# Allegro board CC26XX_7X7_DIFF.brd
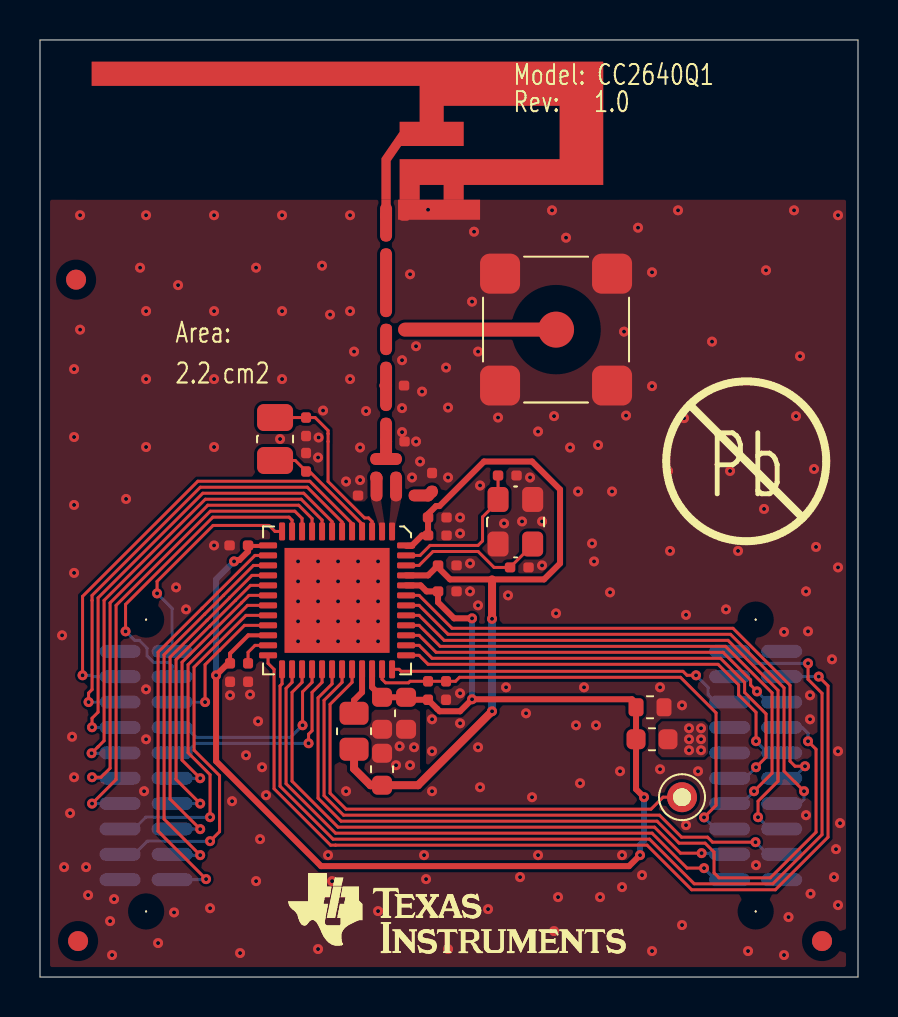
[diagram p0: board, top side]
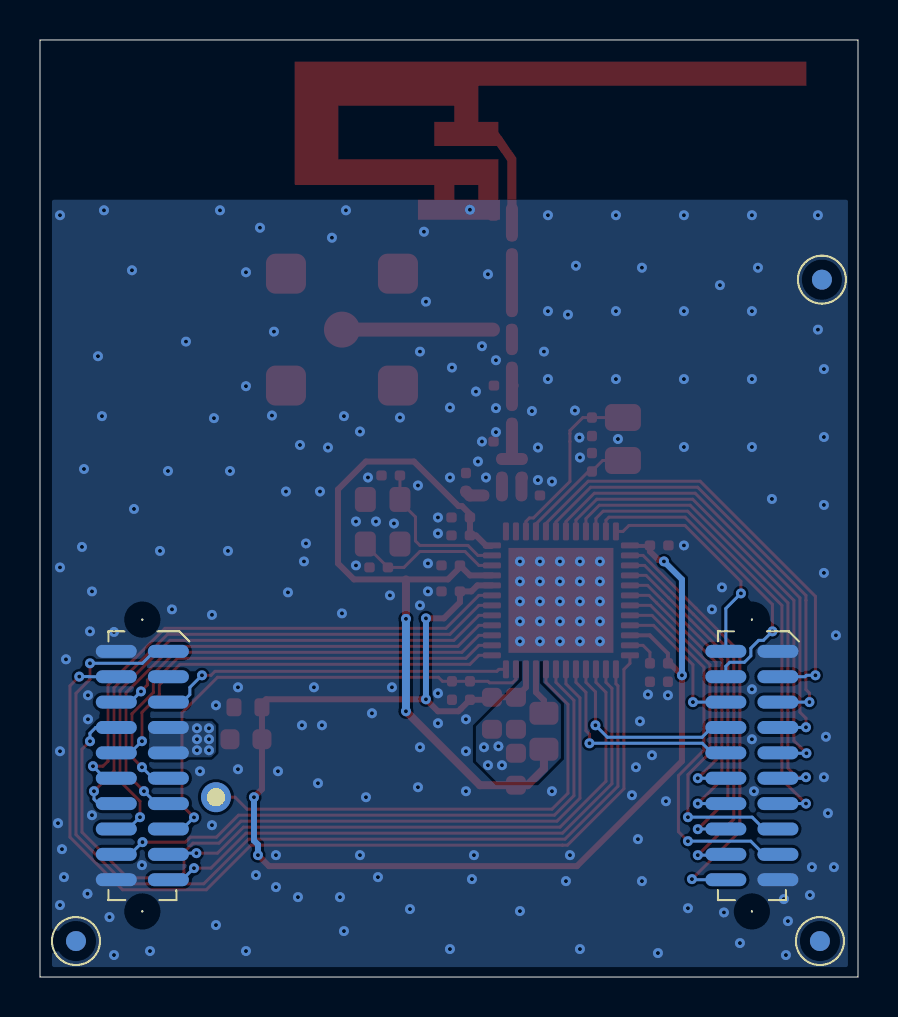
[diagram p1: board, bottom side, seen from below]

Outline 40.9 x 46.9 mm; copper layers: TOP, BOTTOM. Coordinates in mm from the lower left corner of the outline.
Outline path: 0,46.9 0,0 40.9,0 40.9,46.9 0,46.9

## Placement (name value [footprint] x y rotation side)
A1  2.4GHz  [ANTENNA_DN007AN]  17.3 38.65 0 top
C2  DNM  [CAPC1608X90L]  29.8 13.5 0 top
C3  100nF  [CAPC1005X60B2N]  10.4 21.6 180 top
C4  100nF  [CAPC1005X60B2N]  9.5 15.7 270 top
C5  100nF  [CAPC1005X60B2N]  19.9 19.3 0 top
C6  10uF  [CAPC1608X100A2N]  17.1 14 270 top
C7  100nF  [CAPC1608X90A2N]  18.3 14 270 top
C8  10uF  [CAPC1608X100A2N]  17.1 9.6 90 top
C9  100nF  [CAPC1005X60B2N]  19.9 20.6 0 top
C10  DNM_0402  [CAPC1005X60B2N]  19.4 23 0 top
C11  1pF  [CAPC1005X60B2N]  17.8 25 90 top
C12  DNM_0402  [CAPC1005X60B2N]  17.3 26.8 0 top
C13  1pF  [CAPC1005X60B2N]  18.2 29.6 180 top
C14  12pF  [CAPC1005X60B2N]  17.3 32.4 90 top
C15  DNM_0402  [CAPC1005X60B2N]  17.3 38.1 0 top
C16  100nF  [CAPC1005X60B2N]  19.4 22.1 0 top
C17  16pF  [CAPC1005X60B2N]  13.3 28 270 top
C18  16pF  [CAPC1005X60B2N]  13.3 25.3 90 top
C19  1uF  [CAPC1005X60B2N]  10.4 15.7 270 top
C20  100nF  [CAPC1005X60B2N]  20.3 14.8 270 top
C21  1pF  [CAPC1005X60B2N]  15.9 24.1 0 top
C22  DNM_0402  [CAPC1005X60B2N]  23.5 20.5 0 top
C23  DNM_0402  [CAPC1005X60B2N]  22.9 25.1 0 top
C24  DNM_0402  [CAPC1005X60B2N]  18.25 32.4 180 top
C31  6.8pF  [CAPC1005X60B2N]  19.6 24.3 90 top
DIO22  TP_0.9mm_PTH  [TP150_90H]  32.1 9 0 top
FIDU1  FIDU_1MM  [FID100X115]  1.9 1.8 0 top
FIDU2  FIDU_1MM  [FID100X115]  39.1 1.8 0 top
FIDU3  FIDU_1MM  [FID100X115]  1.8 34.9 0 top
FIDU4  FIDU_1MM  [FID100X115]  1.9 1.8 180 bottom
FIDU5  FIDU_1MM  [FID100X115]  39.1 1.8 180 bottom
FIDU6  FIDU_1MM  [FID100X115]  1.8 34.9 180 bottom
FL1  BLM18HE152SZ1  [FILC1608X100A2N]  31.4 11.9 180 top
J1  SMA-10V21-TGG  [HUSTSAN_SMA10V21TGGAN]  25.8 32.4 0 top
L1  10uH  [INDC2012X150A2N]  15.7 13.2 270 top
L11  2.4nH  [INDC1005X60B2N]  17.8 24.1 0 top
L12  2nH  [INDC1005X60B2N]  17.3 27.7 90 top
L13  2nH  [INDC1005X60B2N]  17.3 30.5 90 top
L21  2.4nH  [INDC1005X60B2N]  16.8 25 90 top
NOREF  -  []  32.36 0 90 top
NOREF#2  -  []  0 44.07 0 top
P1  SFM-110-02-S-D-A-K-TR  [SAMTEC_SFM11002AN]  4 16.3 0 bottom
P2  SFM-110-02-S-D-A-K-TR  [SAMTEC_SFM11002AN]  34.48 16.3 0 bottom
R1  100k  [RESC1005X40B2N]  19.4 14.8 270 top
R12  0  [RESC1005X40B2N]  17.3 37.1 270 top
U1  CC2640R2FTWRGZRQ1  [QFNFC50P700X700X100-49A2N]  17.6 22.3 180 top
UNK#REFDES  -  []  13.4 5.2 0 top
UNK#REFDES#2  #VALUE  []  31.1 21.6 0 top
Y1  32.768kHz  [XTAL_FC13A_A2N]  11.75 28 270 top
Y2  24MHz  [OSCCC250X320X60-4L]  22.9 23.9 270 top

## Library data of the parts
A1 = ANTENNA_DN007
C2 = CAPACITOR: alternate symbols: (CAPC1608X90L,CAPC1608X90M)
C3-C5 C9-C24 C31 = CAPACITOR: User Part Number: #PN
C6 C8 = CAPACITOR: User Part Number: #PN; alternate symbols: (CAPC1608X100A2L,CAPC1608X100A2M)
C7 = CAPACITOR: User Part Number: #PN; alternate symbols: (CAPC1608X90A2L,CAPC1608X90A2M)
DIO22 = TEST_POINT
FIDU1-FIDU6 = FIDMARK
FL1 = FILTER_FERRITE: User Part Number: #PN; alternate symbols: (FILC1608X100A2L,FILC1608X100A2M)
J1 = CONN_COAX_1+4: alternate symbols: (HUSTSAN_SMA10V21TGGL,HUSTSAN_SMA10V21TGGM)
L1 = IND_CORE: User Part Number: #PN; alternate symbols: (INDC2012X150A2L,INDC2012X150A2M)
L11-L13 L21 = INDUCTOR: User Part Number: #PN
P1 P2 = CONN_HEADER_2X10_P_S
R1 R12 = RESISTOR: User Part Number: #PN; alternate symbols: (RESC1005X40B2L,RESC1005X40B2M)
U1 = IC_RF_CC26XX_QFN48_V2: User Part Number: #PN; alternate symbols: (QFNFC50P700X700X100-49A2L,QFNFC50P700X700X100-49A2M)
UNK#REFDES#2 = -: User Part Number: #PN
Y1 = CRYSTAL: User Part Number: #PN; alternate symbols: (XTAL_FC13A_A2L,XTAL_FC13A_A2M)
Y2 = XTAL_4PIN_S: alternate symbols: (OSCCC250X320X60-4L,OSCCC250X320X60-4M)

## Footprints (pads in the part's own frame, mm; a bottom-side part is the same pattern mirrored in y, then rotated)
ANTENNA_DN007AN
  rect 0.46x0.5 smd: 1(0,0)
  rect 1x0.5 smd: 2(1.18,0) 3(3.38,0)
CAPC1005X60B2N
  custom 0.125x0.125 smd: 1(0,0) 2(0.924,0)
CAPC1608X90A2N
  custom 0.237x0.237 smd: 1(0,0) 2(1.6,0)
CAPC1608X90L
  custom 0.188x0.188 smd: 1(0,0) 2(1.4,0)
CAPC1608X100A2N
  custom 0.237x0.237 smd: 1(0,0) 2(1.6,0)
FID100X115
  round 1 smd: 1(0,0)
FILC1608X100A2N
  custom 0.237x0.237 smd: 1(0,0) 2(1.6,0)
HUSTSAN_SMA10V21TGGAN
  round 1.801 smd: 1(0,0)
  custom 0.5x0.5 smd: 2(-2.8,-2.8) 3(2.8,-2.8) 4(2.8,2.8) 5(-2.8,2.8)
INDC1005X60B2N
  custom 0.125x0.125 smd: 1(0,0) 2(0.924,0)
INDC2012X150A2N
  custom 0.287x0.287 smd: 1(0,0) 2(1.8,0)
OSCCC250X320X60-4L
  custom 0.263x0.263 smd: 1(0,0) 2(2.23,0) 3(2.23,1.73) 4(0,1.73)
QFNFC50P700X700X100-49A2N
  custom 0.075x0.075 smd: 1(0,0) 2(0.5,0) 3(1,0) 4(1.5,0) 5(2,0) 6(2.5,0) 7(3,0) 8(3.5,0) 9(4,0) 10(4.5,0) 11(5,0) 12(5.5,0) 13(6.2,0.7) 14(6.2,1.2) 15(6.2,1.7) 16(6.2,2.2) 17(6.2,2.7) 18(6.2,3.2) 19(6.2,3.7) 20(6.2,4.2) 21(6.2,4.7) 22(6.2,5.2) 23(6.2,5.7) 24(6.2,6.2) 25(5.5,6.9) 26(5,6.9) 27(4.5,6.9) 28(4,6.9) 29(3.5,6.9) 30(3,6.9) 31(2.5,6.9) 32(2,6.9) 33(1.5,6.9) 34(1,6.9) 35(0.5,6.9) 36(0,6.9) 37(-0.7,6.2) 38(-0.7,5.7) 39(-0.7,5.2) 40(-0.7,4.7) 41(-0.7,4.2) 42(-0.7,3.7) 43(-0.7,3.2) 44(-0.7,2.7) 45(-0.7,2.2) 46(-0.7,1.7) 47(-0.7,1.2) 48(-0.7,0.7)
  rect 5.25x5.25 smd: 49(2.75,3.45)
RESC1005X40B2N
  custom 0.125x0.125 smd: 1(0,0) 2(0.924,0)
SAMTEC_SFM11002AN
  round 0.099 hole 1.501 unplated: (1.302,-1.588) (1.302,13.017)
  oval 2.05x0.65 smd: 1(0,0) 2(2.604,0) 3(0,1.27) 4(2.604,1.27) 5(0,2.54) 6(2.604,2.54) 7(0,3.81) 8(2.604,3.81) 9(0,5.08) 10(2.604,5.08) 11(0,6.35) 12(2.604,6.35) 13(0,7.62) 14(2.604,7.62) 15(0,8.89) 16(2.604,8.89) 17(0,10.16) 18(2.604,10.16) 19(0,11.43) 20(2.604,11.43)
TP150_90H
  round 1.5 hole 0.9: 1(0,0)
XTAL_FC13A_A2N
  custom 0.338x0.338 smd: 1(0,0) 2(2.15,0)

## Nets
GND: A1.2(GND_2) A1.3(GND_3) C2.2 C3.2 C4.2 C5.2 C6.2 C7.2 C8.2 C9.2 C10.2 C12.2 C13.1 C15.2 C16.2 C17.2 C18.2 C19.2 C20.2 C21.1 C22.2 C23.2 C31.2 J1.2 J1.3 J1.4 J1.5 P1.1 P1.19 P2.2 P2.20 U1.49(VSS) Y2.2 Y2.4
VDD_EB: FL1.1 P2.7 P2.9
VDDR: C8.1 C9.1 C10.1 C16.1 L1.2 U1.45(VDDR#45) U1.48(VDDR#48)
VDDS: C2.1 C3.1 C4.1 C5.1 C6.1 C7.1 FL1.2 R1.2 U1.13(VDDS2) U1.22(VDDS3) U1.34(VDDS_DCDC) U1.44(VDDS)
DCDC_SW: L1.1 U1.33(DCDC_SW)
DIO_0: P1.3 U1.5(DIO_0)
DIO_1: P1.5 U1.6(DIO_1)
DIO_2: P1.7 U1.7(DIO_2)
DIO_3: P1.9 U1.8(DIO_3)
DIO_4: P1.11 U1.9(DIO_4)
DIO_5: P1.13 U1.10(DIO_5)
DIO_6: P1.4 U1.11(DIO_6)
DIO_7: P1.2 U1.12(DIO_7)
DIO_8: P1.20 U1.14(DIO_8)
DIO_9: P1.18 U1.15(DIO_9)
DIO_10: P1.16 U1.16(DIO_10)
DIO_11: P1.14 U1.17(DIO_11)
DIO_12: P1.12 U1.18(DIO_12)
DIO_13: P1.15 U1.19(DIO_13)
DIO_14: P1.17 U1.20(DIO_14)
DIO_15: P1.6 U1.21(DIO_15)
DIO_16 / JTAG TDO: P2.19 U1.26(DIO_16)
DIO_17 / JTAG TDI: P2.17 U1.27(DIO_17)
DIO_18: P1.8 U1.28(DIO_18)
DIO_19: P1.10 U1.29(DIO_19)
DIO_20: P2.8 U1.30(DIO_20)
DIO_21: P2.18 U1.31(DIO_21)
DIO_22: DIO22.1 U1.32(DIO_22)
DIO_23: P2.5 U1.36(DIO_23)
DIO_24: P2.10 U1.37(DIO_24)
DIO_25: P2.11 U1.38(DIO_25)
DIO_26: P2.6 U1.39(DIO_26)
DIO_27: P2.13 U1.40(DIO_27)
DIO_28: P2.16 U1.41(DIO_28)
DIO_29: P2.14 U1.42(DIO_29)
DIO_30: P2.12 U1.43(DIO_30)
JTAG_TCK: P2.1 U1.25(JTAG_TCKC)
JTAG_TMS: P2.4 U1.24(JTAG_TMSC)
NRESET: C20.1 P2.15 R1.1 U1.35(RESET_N)
N310466: C23.1 U1.47(X24M_P) Y2.1
N310868: C22.1 U1.46(X24M_N) Y2.3
N314427: C21.2 L21.1 U1.2(RF_N)
N314470: C11.1 L11.1 U1.1(RF_P)
N314514: C31.1 L11.2
N314764: C11.2 C12.1 L12.1 L21.2
N315193: C13.2 L12.2 L13.1
N316022: A1.1(FEED_1) C15.1 R12.1
N316040: C24.1 J1.1
N316649: C19.1 U1.23(DCOUPL)
N316919: C17.1 U1.3(X32K_Q1) Y1.1
N316932: C18.1 U1.4(X32K_Q2) Y1.2
N334495: C14.1 C24.2 L13.2
N356130: C14.2 R12.2

Pads without a net: FIDU1 1; FIDU2 1; FIDU3 1; FIDU4 1; FIDU5 1; FIDU6 1; P2 3

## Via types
v1: diameter 0.5, hole 0.2, TOP to BOTTOM, 260 vias

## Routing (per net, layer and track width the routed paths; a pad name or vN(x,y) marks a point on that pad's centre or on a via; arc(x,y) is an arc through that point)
GND:
  vias: v1(1.1,17.1) v1(1.2,5.5) v1(1.5,8.2) v1(1.6,12.02) v1(1.7,30.42) v1(1.7,27.02) v1(1.7,23.62) v1(1.7,20.22) v1(1.7,10) v1(2,38.12) v1(2,32.4) v1(2.3,5.5) v1(2.4,4.1) v1(3.5,2.8) v1(3.6,1.1) v1(3.7,3.9) v1(4.3,23.92) v1(5,35.5) v1(5.2,9.3) v1(5.3,38.12) v1(5.3,33.33) v1(5.3,29.92) v1(5.3,26.52) v1(5.3,14.4) v1(5.3,11.9) v1(5.9,1.7) v1(6.7,3.23) v1(6.8,19.5) v1(6.9,34.62) v1(7.3,18.4) v1(8.5,3.44) v1(8.7,38.12) v1(8.7,33.33) v1(8.7,29.92) v1(8.7,26.52) v1(8.7,21.6) v1(9.5,14.1) v1(9.6,8.8) v1(10,1.2) v1(10.3,11.1) v1(10.5,14.14) v1(10.8,35.5) v1(10.8,4.8) v1(10.9,12.8) v1(11,6.9) v1(11.1,10.5) v1(11.3,9.1) v1(12,26.92) v1(12.1,38.12) v1(12.1,33.33) v1(12.1,29.92) v1(12.9,20.8) v1(12.9,19.8) v1(12.9,18.8) v1(12.9,17.8) v1(12.9,16.8) v1(13.93,27) v1(13.9,26) v1(13.9,20.8) v1(13.9,19.8) v1(13.9,18.8) v1(13.9,17.8) v1(13.9,16.8) v1(13.9,1.4) v1(14.1,35.6) v1(14.15,28.35) v1(14.4,6.1) v1(14.5,33.15) v1(14.6,4.8) v1(14.9,20.8) v1(14.9,19.8) v1(14.9,18.8) v1(14.9,17.8) v1(14.9,16.8) v1(15.3,24.8) v1(15.3,9.3) v1(15.5,38.12) v1(15.5,33.33) v1(15.5,29.92) v1(15.7,31.3) v1(15.9,20.8) v1(15.9,19.8) v1(15.9,18.8) v1(15.9,17.8) v1(15.9,16.8) v1(16,26.5) v1(16,24.87) v1(16.3,28.33) v1(16.9,20.8) v1(16.9,19.8) v1(16.9,18.8) v1(16.9,17.8) v1(16.9,16.8) v1(16.9,3.3) v1(17.8,10.6) v1(17.98,11.55) v1(18.1,30.87) v1(18.1,28.47) v1(18.1,27.27) v1(18.5,35.17) v1(18.5,10.6) v1(18.6,25) v1(18.7,11.5) v1(18.8,31.57) v1(18.8,26.8) v1(19,25.8) v1(19.1,29.3) v1(19.2,6.1) v1(19.3,4.9) v1(19.4,38.4) v1(19.6,12.9) v1(19.6,11.3) v1(19.6,9.3) v1(20.3,30.5) v1(20.4,28.5) v1(20.4,25) v1(20.4,1.4) v1(21,23) v1(21,22.2) v1(21,14.2) v1(21,12.7) v1(21.5,20.7) v1(21.5,19.3) v1(21.6,33.8) v1(21.7,37.3) v1(21.9,31.3) v1(21.9,18.6) v1(21.9,11.5) v1(22,24.6) v1(22,9.5) v1(22.4,3.4) v1(22.9,28) v1(23.2,22.7) v1(23.3,14.5) v1(23.4,19.1) v1(24,5) v1(24.1,22.8) v1(24.3,13.2) v1(24.5,25) v1(24.6,9) v1(24.9,27.3) v1(24.9,6.1) v1(25.1,22.8) v1(25.1,20.6) v1(25.6,38.37) v1(25.7,28.07) v1(25.7,2.3) v1(25.8,18.2) v1(25.9,4) v1(26.3,37) v1(26.5,26.5) v1(26.8,12.6) v1(26.9,24.3) v1(27,9.7) v1(27.2,14.5) v1(27.6,21.7) v1(27.7,20.8) v1(27.8,12.6) v1(27.9,26.62) v1(28,4) v1(28.5,19.25) v1(28.6,24.3) v1(29,10.3) v1(29.1,6.1) v1(29.1,4.5) v1(29.2,32.3) v1(29.3,28.1) v1(29.9,37.5) v1(30.1,5.1) v1(30.6,35.27) v1(30.6,29.57) v1(30.6,1.3) v1(31,14.5) v1(31,10.4) v1(31.4,25.33) v1(31.5,21.33) v1(31.9,38.37) v1(32.1,13.6) v1(32.1,2.6) v1(32.2,27.97) v1(32.3,18.12) v1(32.3,7.6) v1(32.9,10.3) v1(33.6,31.8) v1(34.3,18.4) v1(34.5,25.33) v1(34.9,21.33) v1(35.4,1.3) v1(35.8,5.6) v1(36.2,23.42) v1(36.3,35.37) v1(37.2,17.27) v1(37.2,1.1) v1(37.43,3) v1(37.7,38.37) v1(37.8,28.07) v1(38,31.07) v1(38.3,19.3) v1(38.3,8.1) v1(38.4,17.3) v1(38.5,14.1) v1(38.5,12.9) v1(38.53,4.17) v1(38.7,25.42) v1(38.8,21.52) v1(39.6,15.9) v1(39.7,5) v1(39.8,6.4) v1(39.9,38.12) v1(39.9,20.5) v1(39.9,11.3) v1(39.9,3.6) v1(40,7.7)
VDD_EB:
  vias: v1(32.45,12.45) v1(32.45,11.9) v1(32.45,11.35) v1(33.05,12.45) v1(33.05,11.9) v1(33.05,11.35)
VDDR: length 39.3
  TOP w0.15: U1.48 18.33,21.58
  TOP w0.3: U1.45 19.4,20.1 C9.1 19.9,20.5 20.5,19.9 25.2,19.9 26,20.7 26,24.4 24.6,25.8 22.2,25.8 19.97,23.57 19.8,23.57 19.4,23.17 C10.1 C16.1 19.1,22.1 18.58,21.58 18.33,21.58
  TOP w0.4: v1(22.6,17.93) 22.6,19.9 ; v1(22.6,13.3) 18.9,9.6 C8.1 16.53,9.6 15.7,10.42 L1.2
  BOTTOM w0.4: v1(22.6,13.3) v1(22.6,17.93)
VDDS: length 71
  TOP w0.15: U1.34 16.6,15.35 ; U1.13 11.38,21.58
  TOP w0.2: U1.22 10.41,17.1 9.5,16.19 C4.1 ; 11.38,21.58 10.43,21.58 C3.1
  TOP w0.3: C4.1 9.41,15.7 v1(8.8,15.1) 8.8,10.8 14.05,5.55 29.45,5.55 v1(30,6.1) ; C3.1 10.4,21.3 9.98,20.87 9.78,20.87 v1(9.7,20.8) ; U1.44 19.03,19.6 19.33,19.3 C5.1 19.9,18.75 20.71,17.95 v1(21.6,17.95) ; 16.6,15.35 16.6,14.5 C6.1 C7.1 18.43,13.88 R1.2 19.86,13.42 19.98,13.3 21,13.3 v1(21.6,13.9) 29.6,13.9 29.8,13.69 C2.1 FL1.2 29.8,9.4 v1(30.2,9)
  BOTTOM w0.3: v1(9.7,20.8) 8.8,19.9 v1(8.8,15.1) ; v1(21.6,13.9) v1(21.6,17.95) ; v1(30,6.1) 30,6.63 30.2,6.83 v1(30.2,9)
DCDC_SW: length 2.4
  TOP w0.15: U1.33 16.1,15.35
  TOP w0.3: 16.1,15.35 16.1,14.25 15.7,13.85 L1.1
DIO_0: length 23
  TOP w0.15: v1(2.13,15.1) 2.13,19.05 7.89,24.81 13.49,24.81 15.6,22.7 U1.5
  BOTTOM w0.15: v1(2.13,15.1) 2.58,15.1 2.65,15.03 P1.3
DIO_1: length 22.9
  TOP w0.15: U1.6 15.1,22.77 13.37,24.51 8.02,24.51 2.6,19.1 2.6,18.85 2.6,18.85 2.6,14.39 2.43,14.21 v1(2.43,13.76)
  BOTTOM w0.15: v1(2.43,13.76) P1.5
DIO_2: length 23
  TOP w0.15: U1.7 14.6,22.79 13.19,24.21 8.14,24.21 2.9,18.97 2.9,13.25 2.6,12.95 v1(2.6,12.5)
  BOTTOM w0.15: P1.7 2.81,12.49 2.8,12.5 v1(2.6,12.5)
DIO_3: length 23.3
  TOP w0.15: v1(2.58,11.2) 2.9,11.52 3.2,11.82 3.2,18.85 8.27,23.91 13.06,23.91 14.1,22.87 U1.8
  BOTTOM w0.15: v1(2.58,11.2) 3.98,11.2 P1.9
DIO_4: length 23.8
  TOP w0.15: U1.9 13.6,22.94 12.94,23.61 8.39,23.61 3.5,18.72 3.5,10.45 3.05,10 v1(2.6,10)
  BOTTOM w0.15: P1.11 2.85,9.95 2.8,10 v1(2.6,10)
DIO_5: length 23.9
  TOP w0.15: U1.10 13.1,22.95 12.74,23.31 8.52,23.31 3.8,18.6 3.8,9.88 v1(2.6,8.68)
  BOTTOM w0.15: P1.13 v1(2.6,8.68)
DIO_6: length 15.9
  TOP w0.15: v1(4.28,17.3) 4.28,18.65 8.64,23.01 12.45,23.01 12.6,22.86 U1.11
  BOTTOM w0.15: v1(4.28,17.3) 4.73,16.85 4.96,16.85 5.36,16.46 5.36,16.07 5.68,15.75 6.42,15.75 6.61,15.56 P1.4
DIO_7: length 11.3
  TOP w0.15: v1(5.85,19.2) 5.85,19.8 8.65,22.6 11.45,22.6 11.75,22.3 U1.12
  BOTTOM w0.15: P1.2 6.61,18.45 v1(5.85,19.2)
DIO_8: length 21.6
  TOP w0.15: U1.14 10.75,21.1 8.88,19.23 5.9,16.26 5.9,7.3 v1(8.3,4.9)
  BOTTOM w0.15: v1(8.3,4.9) 8.27,4.87 P1.20
DIO_9: length 19.2
  TOP w0.15: U1.15 10.67,20.6 9.18,19.1 9.18,19.1 8.23,18.16 6.2,16.13 6.2,7.91 v1(8.01,6.1)
  BOTTOM w0.15: v1(8.01,6.1) 6.65,6.1 P1.18
DIO_10: length 17.2
  TOP w0.15: v1(8.01,7.4) 6.5,8.91 6.5,16.01 8.36,17.86 8.36,17.86 9.48,18.98 9.48,18.98 10.6,20.1 U1.16
  BOTTOM w0.15: v1(8.01,7.4) 7.84,7.4 7.84,7.41 P1.16
DIO_11: length 15.2
  TOP w0.15: v1(8.01,8.68) 6.8,9.89 6.8,15.88 8.48,17.56 8.48,17.56 9.78,18.85 10.52,19.6 U1.17
  BOTTOM w0.15: v1(8.01,8.68) P1.14
DIO_12: length 13.3
  TOP w0.15: v1(8.01,9.95) 7.1,10.86 7.1,15.76 8.61,17.26 10.45,19.1 U1.18
  BOTTOM w0.15: v1(8.01,9.95) P1.12
DIO_13: length 18.1
  TOP w0.15: U1.19 10.37,18.6 8.73,16.96 7.4,15.63 7.4,11.23 8.5,10.13 v1(8.5,8)
  BOTTOM w0.15: v1(8.5,8) 5.29,8 4.7,7.41 P1.15
DIO_14: length 19
  TOP w0.15: U1.20 10.3,18.1 8.86,16.66 8.86,16.66 7.7,15.51 7.7,11.35 8.98,10.08 8.98,7.27 v1(8.5,6.8)
  BOTTOM w0.15: v1(8.5,6.8) 5.36,6.8 4.7,6.14 P1.17
DIO_15: length 7.5
  TOP w0.15: U1.21 10.22,17.6 8.98,16.36 8.98,16.36 8.25,15.63 v1(8.25,13.76)
  BOTTOM w0.15: P1.6 v1(8.25,13.76)
DIO_16 / JTAG TDO: length 30
  TOP w0.15: v1(33.2,5.45) 32.35,5.45 30.6,7.2 14.78,7.2 12.3,9.67 12.3,14.45 12.6,14.75 U1.26
  BOTTOM w0.15: P2.19 33.78,4.87 v1(33.2,5.45)
DIO_17 / JTAG TDI: length 29.2
  TOP w0.15: v1(33.08,6.2) 32.03,6.2 30.73,7.5 14.9,7.5 12.6,9.8 12.6,14.25 13.1,14.75 U1.27
  BOTTOM w0.15: P2.17 33.78,6.14 33.72,6.2 v1(33.08,6.2)
DIO_18: length 10
  TOP w0.15: v1(13.13,12.6) 13.13,14.27 13.6,14.75 U1.28
  BOTTOM w0.15: P1.8 7.31,12.49 7.8,12 12.53,12 v1(13.13,12.6)
DIO_19: length 11
  TOP w0.15: U1.29 14.1,14.75 13.6,14.25 13.6,12.33 13.43,12.15 v1(13.43,11.7)
  BOTTOM w0.15: P1.10 7.31,11.22 7.79,11.7 v1(13.43,11.7)
DIO_20: length 41.4
  TOP w0.15: U1.30 14.6,14.67 13.9,13.97 13.9,8.95 15.05,7.8 30.85,7.8 31.95,6.7 33.25,6.7 33.7,6.25 33.7,5.22 33.95,4.97 36.52,4.97 38.8,7.25 38.8,11.4 v1(38.4,11.8)
  BOTTOM w0.15: P2.8 38.11,12.49 38.4,12.2 v1(38.4,11.8)
DIO_21: length 30.8
  TOP w0.15: v1(35.78,6.75) 33.63,6.75 33.38,7 32.08,7 30.98,8.1 15.18,8.1 14.2,9.08 14.2,13.85 15.1,14.75 U1.31
  BOTTOM w0.15: P2.18 36.39,6.14 v1(35.78,6.75)
DIO_22: length 24.8
  TOP w0.15: DIO22.1 31.15,9 30.55,8.4 15.3,8.4 14.5,9.2 14.5,13.65 15.6,14.75 U1.32
DIO_23: length 17.8
  TOP w0.15: v1(32.8,15.1) 32.35,15.1 32.15,15.3 18.06,15.3 17.96,15.4 U1.36
  BOTTOM w0.15: v1(32.8,15.1) 33.41,14.49 33.41,14.13 33.78,13.76 P2.5
DIO_24: length 21.9
  TOP w0.15: v1(35.8,11.8) 35.8,13.25 34.93,14.12 34.93,14.62 33.9,15.65 19.41,15.65 18.96,16.1 U1.37
  BOTTOM w0.15: v1(35.8,11.8) 36.39,11.22 P2.10
DIO_25: length 24.1
  TOP w0.15: U1.38 18.96,16.6 19.61,15.95 34.03,15.95 35.23,14.74 35.23,14.24 36.3,13.17 36.3,11 v1(35.8,10.5)
  BOTTOM w0.15: v1(35.8,10.5) 35.25,9.95 P2.11
DIO_26: length 20.3
  TOP w0.15: U1.39 18.96,17.1 19.81,16.25 34.15,16.25 35.53,14.87 35.53,14.61 v1(35.85,14.29)
  BOTTOM w0.15: P2.6 36.39,13.76 v1(35.85,14.29)
DIO_27: length 26.5
  TOP w0.15: U1.40 18.96,17.6 20.01,16.55 34.28,16.55 36.6,14.22 36.6,10.2 v1(35.7,9.3)
  BOTTOM w0.15: v1(35.7,9.3) 35.08,8.68 P2.13
DIO_28: length 28.4
  TOP w0.15: U1.41 18.96,18.1 20.21,16.85 34.4,16.85 36.9,14.35 36.9,9.8 35.9,8.8 v1(35.9,8)
  BOTTOM w0.15: P2.16 37.08,7.4 36.5,7.4 v1(35.9,8)
DIO_29: length 27.8
  TOP w0.15: U1.42 18.96,18.6 20.41,17.15 34.53,17.15 37.2,14.47 37.2,10.3 v1(38.2,9.3)
  BOTTOM w0.15: P2.14 37.98,8.68 38.2,8.9 v1(38.2,9.3)
DIO_30: length 27.1
  TOP w0.15: v1(38.25,10.55) 37.75,10.55 37.5,10.8 37.5,14.6 34.65,17.45 20.61,17.45 18.96,19.1 U1.43
  BOTTOM w0.15: P2.12 37.65,9.95 v1(38.25,10.55)
JTAG_TCK: length 49.1
  TOP w0.15: U1.25 12.1,14.67 12,14.57 12,9.55 14.65,6.9 30.48,6.9 32.71,4.67 36.64,4.67 39.1,7.12 39.1,14.2 38.4,14.9 v1(38.4,15.7)
  BOTTOM w0.15: v1(38.4,15.7) 35.78,15.7 35.18,16.3 P2.1
JTAG_TMS: length 47.8
  TOP w0.15: U1.24 11.4,15.7 11.7,15.4 11.7,9.42 14.53,6.6 14.78,6.6 14.78,6.6 30.35,6.6 32.59,4.37 36.77,4.37 39.4,7 39.4,14.57 v1(38.94,15.04)
  BOTTOM w0.15: P2.4 38.48,15.03 38.49,15.04 v1(38.94,15.04)
NRESET: length 25.1
  TOP w0.15: v1(33.2,7.99) 33.8,8.59 33.8,13.22 32.03,15 20.98,15 20.78,14.8 C20.1 R1.1 18.5,14.8 18.43,14.72 17.28,14.72 17.1,14.9 U1.35
  BOTTOM w0.15: v1(33.2,7.99) 33.78,7.41 P2.15
N310466: length 7.7
  TOP w0.15: C23.1 Y2.1 22.9,23.8 22.13,23.02 22.13,21.83 21.9,21.6 19.5,21.6 19,21.1 U1.47
N310868: length 7.5
  TOP w0.15: U1.46 18.96,20.6 19.65,21.3 21.91,21.3 22.7,20.5 23.45,20.5 23.5,20.55 C22.1 24.63,21.63 Y2.3
N314427: length 0.9
  TOP w0.6: C21.2 16.83,24.98 L21.1
N314470: length 0.9
  TOP w0.6: L11.1 C11.1
N314514: length 1
  TOP w0.6: L11.2 19.4,24.1 C31.1
N314764: length 2.8
  TOP w0.6: L21.2 17.3,25.92 ; 17.3,25.92 C11.2 ; 17.3,25.92 C12.1 L12.1
N315193: length 1.9
  TOP w0.6: L13.1 17.3,29.62 C13.2 17.3,29.58 L12.2
N316022: length 1.5
  TOP w0.15: A1.1 17.3,38.58
  TOP w0.43: 17.3,38.58 17.3,38.45
  TOP w0.6: R12.1 C15.1 17.3,38.45
N316040: length 7.6
  TOP w0.7: C24.1 J1.1
N316649: length 1.7
  TOP w0.15: C19.1 10.4,16.25 10.75,16.6 U1.23
N316919: length 9
  TOP w0.15: Y1.1 C17.1 13.76,28 14.4,27.35 14.4,27.2 14.41,27.2 14.41,26.8 14.4,26.8 14.4,24.8 16.23,22.97 16.43,22.97 16.6,22.8 U1.3
N316932: length 6
  TOP w0.15: U1.4 16.1,22.67 13.48,25.3 C18.1 13.3,25.31 12.77,25.85 Y1.2
N334495: length 1
  TOP w0.6: L13.2 C14.1
N356130: length 2.9
  TOP w0.6: C14.2 R12.2

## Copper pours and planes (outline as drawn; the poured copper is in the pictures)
GND on TOP (solid shape): 22,37.9 17.9,37.9 17.9,38.9 22,38.9
GND on TOP (solid shape): 28.16,39.64 21.18,39.64 21.18,38.9 20.18,38.9 20.18,39.64 18.98,39.64 18.98,38.9 17.98,38.9 17.98,40.93 25.98,40.93 25.98,43.6 20.18,43.6 20.18,42.8 21.18,42.8 21.18,41.59 18.06,41.59 17.53,40.83 17.53,38.9 17.07,38.9 17.07,40.98 17.98,42.3 17.98,42.8 18.98,42.8 18.98,44.6 2.58,44.6 2.58,45.81 28.16,45.81
GND on TOP: 0.5,0.5 0.5,38.9 40.3,38.9 40.3,0.5 ; 11 cut-outs
GND on BOTTOM: 0.5,0.5 0.5,38.9 40.3,38.9 40.3,0.5 ; 9 cut-outs
VDD_EB on TOP: 31.1,12.8 33.2,12.8 33.4,12.6 33.4,11.2 33.2,11 31.1,11 30.9,11.2 30.9,12.6
VDD_EB on BOTTOM: 32.3,12.8 35.2,12.8 35.45,12.55 35.45,11.15 35.3,11 32.35,11 32.1,11.25 32.1,12.6
N314427 on TOP: 16.54,24.3 16.55,23.85 16.95,22.55 16.95,22.1 17.25,22.1 17.25,22.55 17.05,23.85 17.05,24.3
N314470 on TOP: 18.05,24.3 18.05,23.85 17.75,22.55 17.75,22.1 17.45,22.1 17.45,22.55 17.55,23.85 17.55,24.3

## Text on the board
Ref Des/Silkscreen Top: Area: | 2.2 cm2 | Model: CC2640Q1 | Rev:   1.0
XSECTION_CHART: L1: TOP CONDUCTOR - COPPER 0.035 MM | *  DIELECTRIC - FR-4 0.73 MM | L2: BOTTOM CONDUCTOR - COPPER 0.035 MM | DESIGN CROSS SECTION CHART | ___________________________ | TOTAL THICKNESS 0.8 MM
User.5: FIGURE | SIZE | 0.2 | 0.9 | 1.501 | DRILL CHART: TOP to BOTTOM | ALL UNITS ARE IN MILLIMETERS | PLATED | NON-PLATED | QTY | 232 | 25 | 1 | 4
